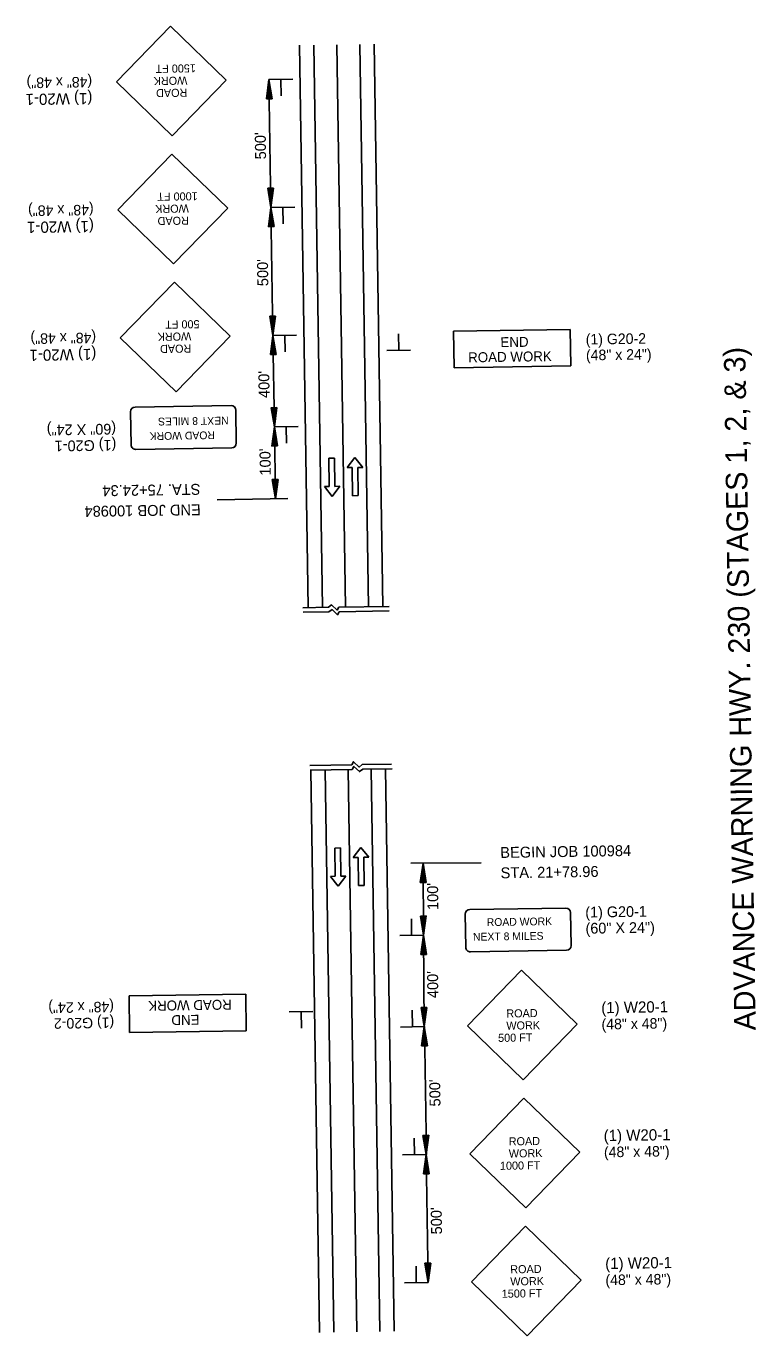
# Model space of a CAD drawing. Extents: x 1770139 to 1773492, y 718230 to 727190.
# Drawn here: x 1771107 to 1771514, y 720575 to 721306 of the extents above; entities that cross this region are included whole.
import ezdxf

# ---------------------------------------------------------------- set-up
doc = ezdxf.new("R2010")
doc.units = 0
for name, color, linetype in [('Default', 7, 'Continuous'), ('R_Dimension', 7, 'Continuous'), ('R_Draft', 7, 'Continuous'), ('R_MOT', 7, 'Continuous')]:
    doc.layers.add(name, color=color, linetype=linetype)

msp = doc.modelspace()

# ---------------------------------------------------------------- linework, layer by layer
at = {"layer": 'Default'}
for p, q in [((1771267.54, 721295.92), (1771272.38, 720981.96)), ((1771280.4, 721296.12), (1771285.24, 720982.16)), ((1771293.26, 721296.32), (1771298.09, 720982.35)), ((1771242.53, 721276.67), (1771243.63, 721205.25)), ((1771243.63, 721205.25), (1771244.73, 721133.83)), ((1771244.73, 721133.83), (1771245.51, 721082.77)), ((1771245.51, 721082.77), (1771246.13, 721042.58)), ((1771275.84, 721065.24), (1771279.05, 721065.29)), ((1771276.08, 721049.48), (1771275.84, 721065.24)), ((1771279.29, 721049.53), (1771279.05, 721065.29)), ((1771286.21, 721060), (1771290.41, 721065.62)), ((1771290.41, 721065.62), (1771294.78, 721060.13)), ((1771286.21, 721060), (1771288.89, 721060.04)), ((1771288.89, 721060.04), (1771289.13, 721044.28)), ((1771292.1, 721060.09), (1771294.78, 721060.13)), ((1771292.1, 721060.09), (1771292.34, 721044.33)), ((1771273.4, 721049.44), (1771276.08, 721049.48)), ((1771273.4, 721049.44), (1771277.77, 721043.94)), ((1771277.77, 721043.94), (1771281.97, 721049.57)), ((1771279.29, 721049.53), (1771281.97, 721049.57)), ((1771213.69, 721042.08), (1771252.97, 721042.69)), ((1771289.13, 721044.28), (1771292.34, 721044.33)), ((1771261.43, 720981.79), (1771275.64, 720982.01)), ((1771261.65, 720979.21), (1771275.86, 720979.43)), ((1771281.51, 720982.1), (1771309.58, 720982.53)), ((1771281.73, 720979.52), (1771309.61, 720979.95)), ((1771288.71, 720894.05), (1771265.27, 720893.69)), ((1771288.94, 720891.48), (1771265.5, 720891.12)), ((1771278.62, 720577.28), (1771273.78, 720891.24)), ((1771291.47, 720577.48), (1771286.64, 720891.44)), ((1771310.93, 720894.4), (1771294.59, 720894.14)), ((1771311.16, 720891.82), (1771294.81, 720891.57)), ((1771304.33, 720577.68), (1771299.49, 720891.64)), ((1771279.19, 720847.57), (1771282.4, 720847.62)), ((1771279.43, 720831.81), (1771279.19, 720847.57)), ((1771282.65, 720831.86), (1771282.4, 720847.62)), ((1771289.56, 720842.33), (1771293.76, 720847.96)), ((1771293.76, 720847.96), (1771298.13, 720842.46)), ((1771289.56, 720842.33), (1771292.24, 720842.37)), ((1771292.24, 720842.37), (1771292.48, 720826.61)), ((1771295.45, 720842.42), (1771298.13, 720842.46)), ((1771295.45, 720842.42), (1771295.7, 720826.66)), ((1771360.91, 720839.34), (1771321.62, 720839.07)), ((1771328.74, 720798.92), (1771328.46, 720839.12)), ((1771276.76, 720831.77), (1771279.43, 720831.81)), ((1771276.76, 720831.77), (1771281.13, 720826.28)), ((1771281.13, 720826.28), (1771285.33, 720831.9)), ((1771282.65, 720831.86), (1771285.33, 720831.9)), ((1771292.48, 720826.61), (1771295.7, 720826.66)), ((1771329.09, 720747.86), (1771328.74, 720798.92)), ((1771330.46, 720676.45), (1771329.36, 720747.87)), ((1771331.29, 720605.02), (1771330.19, 720676.44))]:
    msp.add_line(p, q, dxfattribs=at)
for points in [[(1771281.51, 720982.1), (1771280.55, 720980.43), (1771277.46, 720983.33), (1771275.64, 720982.01)], [(1771281.73, 720979.52), (1771280.77, 720977.85), (1771277.69, 720980.76), (1771275.86, 720979.43)], [(1771288.71, 720894.05), (1771289.67, 720895.72), (1771292.76, 720892.82), (1771294.59, 720894.14)], [(1771288.94, 720891.48), (1771289.89, 720893.14), (1771292.98, 720890.24), (1771294.81, 720891.57)]]:
    msp.add_lwpolyline(points, dxfattribs=at)
at = {"layer": 'R_Dimension'}
for p, q in [((1771259.55, 721295.8), (1771264.38, 720981.83)), ((1771301.26, 721296.44), (1771306.09, 720982.48)), ((1771270.62, 720577.16), (1771265.78, 720891.12)), ((1771312.33, 720577.8), (1771307.49, 720891.76))]:
    msp.add_line(p, q, dxfattribs=at)
at = {"layer": 'R_Draft'}
for p, q in [((1771241.09, 721265.93), (1771242.53, 721276.67)), ((1771244.3, 721265.98), (1771242.53, 721276.67)), ((1771241.35, 721265.93), (1771242.55, 721274.88)), ((1771241.63, 721265.94), (1771242.58, 721273.04)), ((1771241.89, 721265.94), (1771242.61, 721271.25)), ((1771242.17, 721265.95), (1771242.64, 721269.44)), ((1771244.03, 721265.98), (1771242.55, 721274.88)), ((1771243.76, 721265.97), (1771242.58, 721273.04)), ((1771243.49, 721265.97), (1771242.61, 721271.25)), ((1771243.22, 721265.96), (1771242.64, 721269.44)), ((1771241.09, 721265.93), (1771244.3, 721265.98)), ((1771242.44, 721265.95), (1771242.67, 721267.65)), ((1771242.94, 721265.96), (1771242.67, 721267.65)), ((1771245.07, 721215.99), (1771241.86, 721215.94)), ((1771241.86, 721215.94), (1771243.63, 721205.25)), ((1771242.12, 721215.94), (1771243.6, 721207.04)), ((1771242.4, 721215.94), (1771243.57, 721208.88)), ((1771242.66, 721215.95), (1771243.54, 721210.66)), ((1771242.94, 721215.95), (1771243.52, 721212.48)), ((1771243.21, 721215.96), (1771243.49, 721214.27)), ((1771243.71, 721215.96), (1771243.49, 721214.27)), ((1771243.98, 721215.97), (1771243.52, 721212.48)), ((1771244.26, 721215.97), (1771243.54, 721210.66)), ((1771244.53, 721215.98), (1771243.57, 721208.88)), ((1771244.8, 721215.98), (1771243.6, 721207.04)), ((1771245.07, 721215.99), (1771243.63, 721205.25)), ((1771242.19, 721194.51), (1771243.63, 721205.25)), ((1771242.45, 721194.51), (1771243.66, 721203.46)), ((1771245.4, 721194.56), (1771243.63, 721205.25)), ((1771245.13, 721194.56), (1771243.66, 721203.46)), ((1771242.73, 721194.52), (1771243.68, 721201.62)), ((1771242.99, 721194.52), (1771243.71, 721199.83)), ((1771243.27, 721194.53), (1771243.74, 721198.02)), ((1771243.54, 721194.53), (1771243.77, 721196.23)), ((1771244.86, 721194.55), (1771243.68, 721201.62)), ((1771244.59, 721194.55), (1771243.71, 721199.83)), ((1771244.32, 721194.54), (1771243.74, 721198.02)), ((1771244.04, 721194.54), (1771243.77, 721196.23)), ((1771242.19, 721194.51), (1771245.4, 721194.56)), ((1771246.17, 721144.57), (1771242.96, 721144.52)), ((1771242.96, 721144.52), (1771244.73, 721133.83)), ((1771243.22, 721144.52), (1771244.7, 721135.62)), ((1771243.5, 721144.52), (1771244.67, 721137.46)), ((1771243.76, 721144.53), (1771244.64, 721139.24)), ((1771244.04, 721144.53), (1771244.62, 721141.06)), ((1771244.31, 721144.54), (1771244.59, 721142.85)), ((1771244.81, 721144.54), (1771244.59, 721142.85)), ((1771245.08, 721144.55), (1771244.62, 721141.06)), ((1771245.36, 721144.55), (1771244.64, 721139.24)), ((1771245.63, 721144.56), (1771244.67, 721137.46)), ((1771245.9, 721144.56), (1771244.7, 721135.62)), ((1771246.17, 721144.57), (1771244.73, 721133.83)), ((1771243.29, 721123.09), (1771244.73, 721133.83)), ((1771243.55, 721123.09), (1771244.76, 721132.04)), ((1771243.83, 721123.1), (1771244.78, 721130.2)), ((1771246.5, 721123.14), (1771244.73, 721133.83)), ((1771246.23, 721123.14), (1771244.76, 721132.04)), ((1771245.96, 721123.13), (1771244.78, 721130.2)), ((1771243.29, 721123.09), (1771246.5, 721123.14)), ((1771244.1, 721123.1), (1771244.81, 721128.41)), ((1771244.37, 721123.11), (1771244.84, 721126.6)), ((1771244.64, 721123.11), (1771244.87, 721124.81)), ((1771245.69, 721123.13), (1771244.81, 721128.41)), ((1771245.42, 721123.12), (1771244.84, 721126.6)), ((1771245.14, 721123.12), (1771244.87, 721124.81)), ((1771246.96, 721093.51), (1771243.74, 721093.46)), ((1771243.74, 721093.46), (1771245.51, 721082.77)), ((1771244.01, 721093.47), (1771245.49, 721084.56)), ((1771244.28, 721093.47), (1771245.46, 721086.41)), ((1771244.55, 721093.47), (1771245.43, 721088.19)), ((1771244.82, 721093.48), (1771245.4, 721090.01)), ((1771245.1, 721093.48), (1771245.38, 721091.79)), ((1771245.6, 721093.49), (1771245.38, 721091.79)), ((1771245.87, 721093.49), (1771245.4, 721090.01)), ((1771246.15, 721093.5), (1771245.43, 721088.19)), ((1771246.42, 721093.5), (1771245.46, 721086.41)), ((1771246.69, 721093.51), (1771245.49, 721084.56)), ((1771246.96, 721093.51), (1771245.51, 721082.77)), ((1771244.07, 721072.04), (1771245.51, 721082.77)), ((1771244.34, 721072.04), (1771245.54, 721080.98)), ((1771244.61, 721072.04), (1771245.57, 721079.14)), ((1771247.29, 721072.09), (1771245.51, 721082.77)), ((1771247.02, 721072.08), (1771245.54, 721080.98)), ((1771246.75, 721072.08), (1771245.57, 721079.14)), ((1771244.07, 721072.04), (1771247.29, 721072.09)), ((1771244.88, 721072.05), (1771245.6, 721077.36)), ((1771245.16, 721072.05), (1771245.63, 721075.54)), ((1771245.43, 721072.06), (1771245.65, 721073.75)), ((1771246.48, 721072.07), (1771245.6, 721077.36)), ((1771246.2, 721072.07), (1771245.63, 721075.54)), ((1771245.93, 721072.06), (1771245.65, 721073.75)), ((1771247.58, 721053.32), (1771244.36, 721053.27)), ((1771244.36, 721053.27), (1771246.13, 721042.58)), ((1771244.63, 721053.27), (1771246.11, 721044.37)), ((1771244.9, 721053.28), (1771246.08, 721046.21)), ((1771245.17, 721053.28), (1771246.05, 721048)), ((1771245.44, 721053.29), (1771246.02, 721049.81)), ((1771245.72, 721053.29), (1771245.99, 721051.6)), ((1771246.22, 721053.3), (1771245.99, 721051.6)), ((1771246.49, 721053.3), (1771246.02, 721049.81)), ((1771246.77, 721053.31), (1771246.05, 721048)), ((1771247.03, 721053.31), (1771246.08, 721046.21)), ((1771247.31, 721053.32), (1771246.11, 721044.37)), ((1771247.58, 721053.32), (1771246.13, 721042.58)), ((1771326.93, 720828.39), (1771328.46, 720839.12)), ((1771327.2, 720828.4), (1771328.47, 720837.33)), ((1771330.14, 720828.42), (1771328.46, 720839.12)), ((1771329.88, 720828.41), (1771328.47, 720837.33)), ((1771327.47, 720828.4), (1771328.49, 720835.49)), ((1771327.74, 720828.4), (1771328.5, 720833.7)), ((1771328.02, 720828.4), (1771328.51, 720831.89)), ((1771328.28, 720828.4), (1771328.52, 720830.1)), ((1771329.6, 720828.41), (1771328.49, 720835.49)), ((1771329.33, 720828.41), (1771328.5, 720833.7)), ((1771329.06, 720828.41), (1771328.51, 720831.89)), ((1771328.79, 720828.41), (1771328.52, 720830.1)), ((1771326.93, 720828.39), (1771330.14, 720828.42)), ((1771330.18, 720809.66), (1771326.97, 720809.61)), ((1771326.97, 720809.61), (1771328.74, 720798.92)), ((1771327.24, 720809.62), (1771328.71, 720800.71)), ((1771327.51, 720809.62), (1771328.68, 720802.55)), ((1771327.78, 720809.62), (1771328.66, 720804.34)), ((1771328.05, 720809.63), (1771328.63, 720806.15)), ((1771328.32, 720809.63), (1771328.6, 720807.94)), ((1771328.83, 720809.64), (1771328.6, 720807.94)), ((1771329.09, 720809.64), (1771328.63, 720806.15)), ((1771329.37, 720809.65), (1771328.66, 720804.34)), ((1771329.64, 720809.65), (1771328.68, 720802.55)), ((1771329.91, 720809.66), (1771328.71, 720800.71)), ((1771330.18, 720809.66), (1771328.74, 720798.92)), ((1771327.21, 720788.2), (1771328.74, 720798.92)), ((1771327.47, 720788.2), (1771328.75, 720797.13)), ((1771327.75, 720788.2), (1771328.76, 720795.29)), ((1771328.02, 720788.2), (1771328.78, 720793.51)), ((1771330.42, 720788.22), (1771328.74, 720798.92)), ((1771330.15, 720788.22), (1771328.75, 720797.13)), ((1771329.88, 720788.22), (1771328.76, 720795.29)), ((1771329.61, 720788.21), (1771328.78, 720793.51)), ((1771327.21, 720788.2), (1771330.42, 720788.22)), ((1771328.29, 720788.21), (1771328.79, 720791.69)), ((1771328.56, 720788.21), (1771328.8, 720789.9)), ((1771329.34, 720788.21), (1771328.79, 720791.69)), ((1771329.07, 720788.21), (1771328.8, 720789.9)), ((1771330.53, 720758.6), (1771327.32, 720758.55)), ((1771327.32, 720758.55), (1771329.09, 720747.86)), ((1771327.59, 720758.56), (1771329.06, 720749.65)), ((1771327.86, 720758.56), (1771329.04, 720751.5)), ((1771328.13, 720758.56), (1771329.01, 720753.28)), ((1771328.4, 720758.57), (1771328.98, 720755.1)), ((1771328.67, 720758.57), (1771328.95, 720756.88)), ((1771329.18, 720758.58), (1771328.95, 720756.88)), ((1771329.45, 720758.59), (1771328.98, 720755.1)), ((1771329.72, 720758.59), (1771329.01, 720753.28)), ((1771329.99, 720758.59), (1771329.04, 720751.5)), ((1771330.27, 720758.6), (1771329.06, 720749.65)), ((1771330.53, 720758.6), (1771329.09, 720747.86)), ((1771327.65, 720737.13), (1771329.09, 720747.86)), ((1771327.92, 720737.13), (1771329.12, 720746.08)), ((1771328.19, 720737.13), (1771329.15, 720744.23)), ((1771328.46, 720737.14), (1771329.18, 720742.45)), ((1771330.86, 720737.18), (1771329.09, 720747.86)), ((1771330.6, 720737.17), (1771329.12, 720746.08)), ((1771330.32, 720737.17), (1771329.15, 720744.23)), ((1771330.05, 720737.16), (1771329.18, 720742.45)), ((1771327.65, 720737.13), (1771330.86, 720737.18)), ((1771328.74, 720737.14), (1771329.2, 720740.63)), ((1771329, 720737.15), (1771329.23, 720738.84)), ((1771329.78, 720737.16), (1771329.2, 720740.63)), ((1771329.51, 720737.16), (1771329.23, 720738.84)), ((1771331.63, 720687.18), (1771328.42, 720687.13)), ((1771328.42, 720687.13), (1771330.19, 720676.44)), ((1771328.69, 720687.14), (1771330.16, 720678.23)), ((1771328.96, 720687.14), (1771330.14, 720680.08)), ((1771329.23, 720687.14), (1771330.11, 720681.86)), ((1771329.5, 720687.15), (1771330.08, 720683.68)), ((1771329.78, 720687.15), (1771330.05, 720685.46)), ((1771330.28, 720687.16), (1771330.05, 720685.46)), ((1771330.55, 720687.17), (1771330.08, 720683.68)), ((1771330.83, 720687.17), (1771330.11, 720681.86)), ((1771331.09, 720687.17), (1771330.14, 720680.08)), ((1771331.37, 720687.18), (1771330.16, 720678.23)), ((1771331.63, 720687.18), (1771330.19, 720676.44)), ((1771328.75, 720665.71), (1771330.19, 720676.44)), ((1771331.96, 720665.76), (1771330.19, 720676.44)), ((1771329.02, 720665.71), (1771330.22, 720674.66)), ((1771329.29, 720665.71), (1771330.25, 720672.81)), ((1771329.56, 720665.72), (1771330.28, 720671.03)), ((1771329.84, 720665.72), (1771330.3, 720669.21)), ((1771331.7, 720665.75), (1771330.22, 720674.66)), ((1771331.42, 720665.75), (1771330.25, 720672.81)), ((1771331.16, 720665.74), (1771330.28, 720671.03)), ((1771330.88, 720665.74), (1771330.3, 720669.21)), ((1771328.75, 720665.71), (1771331.96, 720665.76)), ((1771330.11, 720665.73), (1771330.33, 720667.42)), ((1771330.61, 720665.73), (1771330.33, 720667.42)), ((1771332.73, 720615.76), (1771329.52, 720615.71)), ((1771329.52, 720615.71), (1771331.29, 720605.02)), ((1771329.79, 720615.72), (1771331.26, 720606.81)), ((1771330.06, 720615.72), (1771331.24, 720608.66)), ((1771330.33, 720615.72), (1771331.21, 720610.44)), ((1771330.6, 720615.73), (1771331.18, 720612.26)), ((1771330.88, 720615.73), (1771331.15, 720614.04)), ((1771331.38, 720615.74), (1771331.15, 720614.04)), ((1771331.65, 720615.75), (1771331.18, 720612.26)), ((1771331.93, 720615.75), (1771331.21, 720610.44)), ((1771332.19, 720615.75), (1771331.24, 720608.66)), ((1771332.47, 720615.76), (1771331.26, 720606.81)), ((1771332.73, 720615.76), (1771331.29, 720605.02))]:
    msp.add_line(p, q, dxfattribs=at)
at = {"layer": 'R_MOT'}
for p, q in [((1771157.38, 721275.36), (1771187.56, 721306.45)), ((1771187.56, 721306.45), (1771218.68, 721276.3)), ((1771188.5, 721245.18), (1771218.68, 721276.3)), ((1771255.76, 721276.87), (1771242.53, 721276.67)), ((1771249.18, 721276.58), (1771249.32, 721267.54)), ((1771157.38, 721275.36), (1771188.5, 721245.18)), ((1771158.22, 721203.93), (1771188.39, 721235.03)), ((1771188.39, 721235.03), (1771219.51, 721204.88)), ((1771158.22, 721203.93), (1771189.33, 721173.76)), ((1771189.33, 721173.76), (1771219.51, 721204.88)), ((1771256.86, 721205.45), (1771243.63, 721205.25)), ((1771250.28, 721205.16), (1771250.42, 721196.12)), ((1771159.58, 721132.52), (1771189.76, 721163.61)), ((1771189.76, 721163.61), (1771220.88, 721133.46)), ((1771410.6, 721137.19), (1771345.51, 721136.19)), ((1771410.91, 721116.74), (1771410.6, 721137.19)), ((1771159.58, 721132.52), (1771190.7, 721102.34)), ((1771190.7, 721102.34), (1771220.88, 721133.46)), ((1771257.96, 721134.03), (1771244.73, 721133.83)), ((1771251.38, 721133.74), (1771251.52, 721124.7)), ((1771314.96, 721125.68), (1771314.82, 721134.71)), ((1771345.82, 721115.74), (1771345.51, 721136.19)), ((1771321.55, 721125.59), (1771308.31, 721125.39)), ((1771410.91, 721116.74), (1771345.82, 721115.74)), ((1771167.82, 721093.8), (1771221.4, 721094.62)), ((1771165.28, 721091.17), (1771165.56, 721072.73)), ((1771224.02, 721092.08), (1771224.3, 721073.64)), ((1771258.75, 721082.98), (1771245.51, 721082.77)), ((1771252.17, 721082.68), (1771252.31, 721073.65)), ((1771168.18, 721070.19), (1771221.76, 721071.01)), ((1771322.09, 720799.07), (1771322.03, 720808.1)), ((1771352.31, 720792.19), (1771352.03, 720810.63)), ((1771408.15, 720814.08), (1771354.57, 720813.25)), ((1771411.06, 720793.09), (1771410.77, 720811.54)), ((1771315.5, 720798.83), (1771328.74, 720798.92)), ((1771408.51, 720790.47), (1771354.94, 720789.64)), ((1771383.39, 720779.36), (1771353.21, 720748.24)), ((1771414.51, 720749.18), (1771383.39, 720779.36)), ((1771164.47, 720764.98), (1771229.56, 720765.98)), ((1771164.47, 720764.98), (1771164.79, 720744.53)), ((1771229.56, 720765.98), (1771229.87, 720745.53)), ((1771322.5, 720747.96), (1771322.36, 720756.99)), ((1771267.07, 720756.33), (1771253.84, 720756.13)), ((1771260.49, 720756.04), (1771260.63, 720747)), ((1771164.79, 720744.53), (1771229.87, 720745.53)), ((1771329.09, 720747.86), (1771315.86, 720747.66)), ((1771384.33, 720718.08), (1771353.21, 720748.24)), ((1771414.51, 720749.18), (1771384.33, 720718.08)), ((1771384.75, 720707.94), (1771354.58, 720676.82)), ((1771415.87, 720677.76), (1771384.75, 720707.94)), ((1771323.6, 720676.54), (1771323.46, 720685.57)), ((1771330.19, 720676.44), (1771316.96, 720676.24)), ((1771385.7, 720646.67), (1771354.58, 720676.82)), ((1771415.87, 720677.76), (1771385.7, 720646.67)), ((1771385.59, 720636.52), (1771355.41, 720605.4)), ((1771416.71, 720606.34), (1771385.59, 720636.52)), ((1771324.7, 720605.12), (1771324.56, 720614.15)), ((1771331.29, 720605.02), (1771318.06, 720604.82)), ((1771386.53, 720575.24), (1771355.41, 720605.4)), ((1771416.71, 720606.34), (1771386.53, 720575.24))]:
    msp.add_line(p, q, dxfattribs=at)
for centre, start, end in [((1771167.86, 721091.21), 90.88269, 180.88269), ((1771221.44, 721092.04), 0.88269, 90.88269), ((1771168.14, 721072.77), 180.88269, 270.88269), ((1771221.72, 721073.6), 270.88269, 0.88269), ((1771354.61, 720810.67), 90.88269, 180.88269), ((1771408.19, 720811.5), 0.88269, 90.88269), ((1771354.9, 720792.23), 180.88269, 270.88269), ((1771408.47, 720793.05), 270.88269, 0.88269)]:
    msp.add_arc(centre, 2.58, start, end, dxfattribs=at)

# ---------------------------------------------------------------- texts
at = {"layer": 'Default'}
for s, rotation, p in [("500'", 90.88269, (1771240.91, 721232.12)), ("500'", 90.88269, (1771242.16, 721161.34)), ("400'", 90.88269, (1771242.89, 721098.89)), ("100'", 90.88269, (1771243.55, 721055.59)), ('STA. 75+24.34', 180.88269, (1771204.22, 721050.93)), ('END JOB 100984', 180.88269, (1771204.4, 721039.55)), ('BEGIN JOB 100984', 0.88269, (1771371.57, 720842.03)), ('STA. 21+78.96', 0.88269, (1771371.75, 720830.65)), ("100'", 90.88269, (1771337.02, 720813)), ("400'", 90.88269, (1771337.02, 720763.82)), ("500'", 90.88269, (1771338.22, 720703.33)), ("500'", 90.88269, (1771339.05, 720631.9))]:
    msp.add_text(s, height=6.1, rotation=rotation, dxfattribs=at).set_placement(p)
at = {"layer": 'R_Draft'}
msp.add_text('ADVANCE WARNING HWY. 230 (STAGES 1, 2, & 3)', height=12, rotation=90.88269, dxfattribs=at).set_placement((1771514.06, 720745.83))
at = {"layer": 'R_MOT'}
for s, height, rotation, p in [('1500 FT', 4.516, 180.88326, (1771201.7, 721285.23)), ('(48" x 48")', 5.88, 180.88269, (1771143.85, 721278.24)), ('WORK', 4.515, 180.88272, (1771196.93, 721278.37)), ('(1) W20-1', 6.273, 180.88269, (1771143.99, 721269.22)), ('ROAD', 4.516, 180.88314, (1771196.95, 721271.6)), ('1000 FT', 4.516, 180.88326, (1771202.71, 721213.8)), ('(48" x 48")', 5.88, 180.88269, (1771144.69, 721206.82)), ('WORK', 4.515, 180.88272, (1771197.77, 721206.95)), ('(1) W20-1', 6.273, 180.88269, (1771144.83, 721197.79)), ('ROAD', 4.516, 180.88314, (1771197.79, 721200.18)), ('(48" x 48")', 5.88, 180.88269, (1771146.05, 721135.4)), (' 500 FT', 4.516, 180.88326, (1771205.41, 721142.4)), ('WORK', 4.515, 180.88272, (1771199.13, 721135.53)), ('END', 5.557, 0.88269, (1771371.67, 721127.23)), ('(1) G20-2', 5.881, 0.88269, (1771419.23, 721128.68)), ('(1) W20-1', 6.273, 180.88269, (1771146.19, 721126.38)), ('ROAD', 4.516, 180.88314, (1771199.15, 721128.76)), ('ROAD WORK', 5.557, 0.88269, (1771353.66, 721118.74)), ('(48" x 24")', 5.88, 0.88269, (1771419.37, 721119.86)), ('(60" X 24")', 6, 180.88269, (1771157.2, 721084.53)), (' NEXT 8 MILES', 4.3389, 180.88269, (1771221.58, 721088.47)), ('ROAD WORK', 4.339, 180.88269, (1771212.32, 721080.27)), ('(1) G20-1', 6, 180.88269, (1771157.34, 721075.53)), ('(1) G20-1', 6, 0.88269, (1771418.99, 720808.74)), ('ROAD WORK', 4.339, 0.88269, (1771364.02, 720804)), (' NEXT 8 MILES', 4.3389, 0.88269, (1771354.75, 720795.8)), ('(60" X 24")', 6, 0.88269, (1771419.13, 720799.74)), ('(48" x 24")', 5.88, 180.88269, (1771156.01, 720761.85)), ('ROAD WORK', 5.557, 180.88269, (1771221.73, 720762.97)), ('ROAD', 4.516, 0.88314, (1771374.94, 720752.94)), ('(1) W20-1', 6.273, 0.88269, (1771427.9, 720755.32)), ('(1) G20-2', 5.881, 180.88269, (1771156.15, 720753.04)), ('END', 5.557, 180.88269, (1771203.72, 720754.49)), ('WORK', 4.515, 0.88272, (1771374.95, 720746.16)), ('(48" x 48")', 5.88, 0.88269, (1771428.04, 720746.29)), (' 500 FT', 4.516, 0.88326, (1771368.68, 720739.29)), ('ROAD', 4.516, 0.88314, (1771376.3, 720681.52)), ('(1) W20-1', 6.273, 0.88269, (1771429.26, 720683.9)), ('WORK', 4.515, 0.88272, (1771376.32, 720674.75)), ('(48" x 48")', 5.88, 0.88269, (1771429.4, 720674.88)), ('1000 FT', 4.516, 0.88326, (1771371.38, 720667.89)), ('(1) W20-1', 6.273, 0.88269, (1771430.1, 720612.48)), ('ROAD', 4.516, 0.88314, (1771377.14, 720610.1)), ('WORK', 4.515, 0.88272, (1771377.16, 720603.32)), ('(48" x 48")', 5.88, 0.88269, (1771430.24, 720603.45)), ('1500 FT', 4.516, 0.88326, (1771372.39, 720596.47))]:
    msp.add_text(s, height=height, rotation=rotation, dxfattribs=at).set_placement(p)

doc.saveas('drawing.dxf')
